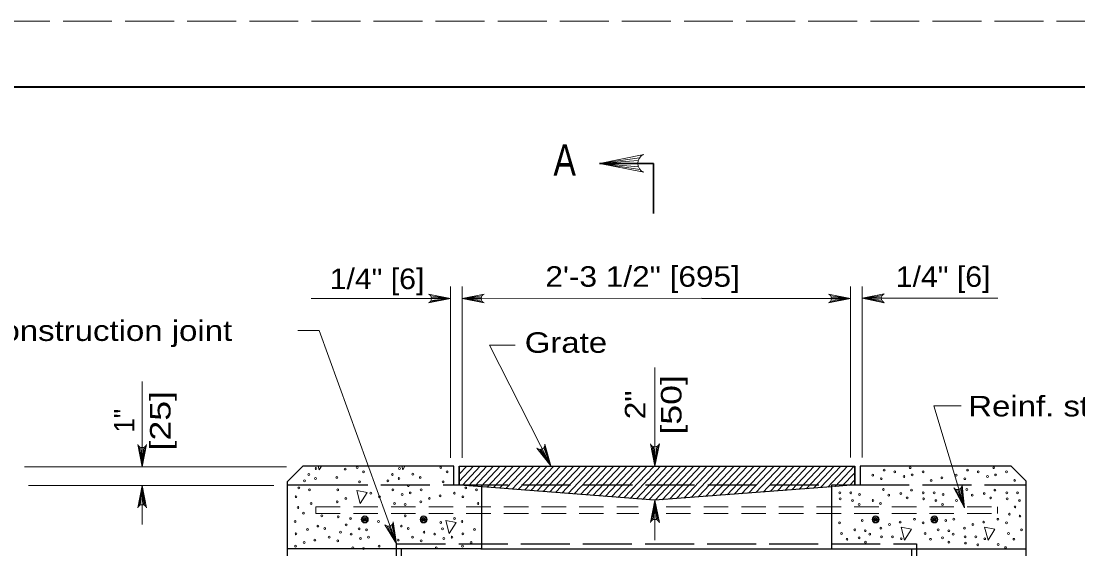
# Model space of a CAD drawing. Extents: x 1083.1 to 1117.1, y 697.4 to 719.4.
# Drawn here: x 1091.89 to 1099.92, y 715.34 to 719.35 of the extents above; entities that cross this region are included whole.
import ezdxf
from ezdxf.enums import TextEntityAlignment as Align

# ---------------------------------------------------------------- set-up
doc = ezdxf.new("R2010")
doc.units = 0
doc.header["$LTSCALE"] = 0.062
doc.linetypes.add('LONG_DASHED', pattern=[7.5, 6, -1.5])
doc.linetypes.add('MEDIUM_DASHED', pattern=[4.5, 3, -1.5])
doc.layers.add('1', color=7, linetype='Continuous', lineweight=13)

msp = doc.modelspace()

# ---------------------------------------------------------------- linework, layer by layer
at = {"layer": '1', "lineweight": 25}
for p, q in [((1085.12642, 718.85408), (1116.62642, 718.85408)), ((1095.18008, 715.82492), (1095.18008, 715.96742)), ((1095.18008, 715.82492), (1095.18008, 715.96742)), ((1095.22233, 715.82492), (1095.22233, 715.96742)), ((1095.22233, 715.96742), (1095.22233, 715.82492)), ((1096.8025, 715.96742), (1098.22792, 715.96742)), ((1098.22792, 715.96742), (1098.22792, 715.82492)), ((1098.22792, 715.82492), (1098.22792, 715.96742)), ((1098.22792, 715.82492), (1098.22792, 715.96742)), ((1098.27017, 715.96742), (1098.27017, 715.82492)), ((1095.18008, 715.82492), (1095.22233, 715.82492)), ((1095.39367, 715.33867), (1095.39367, 715.82492)), ((1098.05058, 715.82492), (1098.05058, 715.33867)), ((1098.22792, 715.82492), (1098.27017, 715.82492)), ((1095.38683, 715.33867), (1093.91333, 715.33867)), ((1094.78358, 711.34008), (1094.78358, 715.33867)), ((1095.38683, 715.33867), (1098.05058, 715.33867)), ((1098.05058, 715.33867), (1098.64775, 715.33867)), ((1098.64775, 715.33867), (1099.53092, 715.33867)), ((1098.65942, 715.33867), (1098.65942, 711.32025))]:
    msp.add_line(p, q, dxfattribs=at)
at = {"layer": '1'}
for p, q in [((1096.59217, 718.31417), (1096.28758, 718.2715)), ((1096.58192, 718.29308), (1096.28758, 718.2715)), ((1096.57875, 718.2715), (1096.28758, 718.2715)), ((1096.58417, 718.24417), (1096.28758, 718.2715)), ((1096.59575, 718.22442), (1096.28758, 718.2715)), ((1095.1565, 716.03125), (1095.1565, 717.33425)), ((1095.243, 716.03142), (1095.243, 717.33425)), ((1098.19683, 716.03333), (1098.19683, 717.33425)), ((1098.28442, 716.0335), (1098.28442, 717.33425)), ((1095.00425, 717.26458), (1095.1565, 717.24325)), ((1095.00942, 717.25408), (1095.1565, 717.24325)), ((1095.39533, 717.26475), (1095.243, 717.24342)), ((1095.39017, 717.25417), (1095.243, 717.24342)), ((1098.0445, 717.26517), (1098.19683, 717.24383)), ((1098.04967, 717.25458), (1098.19683, 717.24383)), ((1098.43675, 717.26683), (1098.28442, 717.2455)), ((1098.43158, 717.25625), (1098.28442, 717.2455)), ((1094.09683, 717.24325), (1095.1565, 717.24325)), ((1095.00242, 717.21975), (1095.1565, 717.24325)), ((1095.00825, 717.22958), (1095.1565, 717.24325)), ((1095.011, 717.24325), (1095.1565, 717.24325)), ((1095.243, 717.24342), (1097.06667, 717.24508)), ((1095.38858, 717.24342), (1095.243, 717.24342)), ((1095.39125, 717.22975), (1095.243, 717.24342)), ((1095.39708, 717.21983), (1095.243, 717.24342)), ((1097.06667, 717.24442), (1098.19683, 717.24383)), ((1098.04275, 717.22033), (1098.19683, 717.24383)), ((1098.04858, 717.23017), (1098.19683, 717.24383)), ((1098.05125, 717.24383), (1098.19683, 717.24383)), ((1098.43, 717.2455), (1098.28442, 717.2455)), ((1098.43267, 717.23183), (1098.28442, 717.2455)), ((1098.4385, 717.222), (1098.28442, 717.2455)), ((1099.31633, 717.2455), (1098.28442, 717.2455)), ((1093.99583, 716.999), (1094.15825, 716.999)), ((1094.15825, 716.999), (1094.74617, 715.37608)), ((1095.45125, 716.8885), (1095.64567, 716.8885)), ((1095.45125, 716.8885), (1095.91917, 715.97025)), ((1096.70908, 715.96925), (1096.70908, 716.71992)), ((1092.8115, 715.96408), (1092.8115, 716.613)), ((1099.06167, 715.65175), (1098.82808, 716.42783)), ((1099.03633, 716.42783), (1098.82808, 716.42783)), ((1096.73258, 716.12333), (1096.70908, 715.96925)), ((1092.79017, 716.11642), (1092.8115, 715.96408)), ((1092.80075, 716.11125), (1092.8115, 715.96408)), ((1092.835, 716.11817), (1092.8115, 715.96408)), ((1092.82517, 716.11242), (1092.8115, 715.96408)), ((1092.8115, 716.10967), (1092.8115, 715.96408)), ((1095.83075, 716.09608), (1095.91917, 715.97025)), ((1095.8425, 716.09633), (1095.91917, 715.97025)), ((1095.85283, 716.09983), (1095.91917, 715.97025)), ((1095.86375, 716.1085), (1095.91917, 715.97025)), ((1095.86983, 716.11817), (1095.91917, 715.97025)), ((1096.68775, 716.1215), (1096.70908, 715.96925)), ((1096.69833, 716.11642), (1096.70908, 715.96925)), ((1096.72275, 716.1175), (1096.70908, 715.96925)), ((1096.70908, 716.11483), (1096.70908, 715.96925)), ((1091.9165, 715.96408), (1093.91008, 715.96408)), ((1095.22233, 715.85258), (1095.33083, 715.96742)), ((1095.22233, 715.90633), (1095.28008, 715.96742)), ((1095.22233, 715.96008), (1095.22933, 715.96742)), ((1095.24533, 715.82308), (1095.38158, 715.96742)), ((1095.29258, 715.81942), (1095.43233, 715.96742)), ((1095.33983, 715.81567), (1095.48308, 715.96742)), ((1095.38708, 715.812), (1095.53383, 715.96742)), ((1095.43433, 715.80833), (1095.58458, 715.96742)), ((1095.48158, 715.80458), (1095.63533, 715.96742)), ((1095.52883, 715.80092), (1095.68617, 715.96742)), ((1095.57608, 715.79717), (1095.73683, 715.96742)), ((1095.62333, 715.7935), (1095.78758, 715.96742)), ((1095.67058, 715.78975), (1095.83833, 715.96742)), ((1095.71783, 715.78608), (1095.88908, 715.96742)), ((1095.76508, 715.78233), (1095.93992, 715.96742)), ((1095.81225, 715.77867), (1095.99058, 715.96742)), ((1095.85958, 715.77492), (1096.04133, 715.96742)), ((1095.90683, 715.77117), (1096.09208, 715.96742)), ((1095.954, 715.7675), (1096.14283, 715.96742)), ((1096.00125, 715.76375), (1096.19367, 715.96742)), ((1096.0485, 715.76008), (1096.24442, 715.96742)), ((1096.09575, 715.75633), (1096.29508, 715.96742)), ((1096.143, 715.75258), (1096.34583, 715.96742)), ((1096.19025, 715.74892), (1096.39658, 715.96742)), ((1096.2375, 715.74517), (1096.44742, 715.96742)), ((1096.28475, 715.7415), (1096.49817, 715.96742)), ((1096.332, 715.73775), (1096.54892, 715.96742)), ((1096.37925, 715.73408), (1096.59958, 715.96742)), ((1096.4265, 715.73033), (1096.65033, 715.96742)), ((1096.47375, 715.72658), (1096.7, 715.96617)), ((1096.61542, 715.71558), (1096.85275, 715.96675)), ((1096.65708, 715.867), (1096.75192, 715.96742)), ((1096.66275, 715.71183), (1096.90275, 715.966)), ((1096.71008, 715.70825), (1096.95492, 715.96742)), ((1096.73483, 715.89558), (1096.80267, 715.96742)), ((1096.76483, 715.71242), (1097.00567, 715.96742)), ((1096.81958, 715.71667), (1097.05642, 715.96742)), ((1096.87433, 715.72083), (1097.10717, 715.96742)), ((1096.929, 715.72508), (1097.15783, 715.96742)), ((1096.98367, 715.72925), (1097.20867, 715.96742)), ((1097.03842, 715.73342), (1097.25942, 715.96742)), ((1097.09317, 715.73767), (1097.31017, 715.96742)), ((1097.14792, 715.74192), (1097.36092, 715.96742)), ((1097.20267, 715.74608), (1097.41167, 715.96742)), ((1097.25742, 715.75033), (1097.46242, 715.96742)), ((1097.31208, 715.75458), (1097.51317, 715.96742)), ((1097.36683, 715.75875), (1097.56392, 715.96742)), ((1097.42158, 715.763), (1097.61467, 715.96742)), ((1097.47633, 715.76717), (1097.66542, 715.96742)), ((1097.531, 715.77133), (1097.71617, 715.96742)), ((1097.58575, 715.77558), (1097.76692, 715.96742)), ((1097.6405, 715.77975), (1097.81767, 715.96742)), ((1097.69525, 715.784), (1097.86842, 715.96742)), ((1097.74992, 715.78825), (1097.91925, 715.96742)), ((1097.80467, 715.79242), (1097.97, 715.96742)), ((1097.85942, 715.79658), (1098.02067, 715.96742)), ((1097.91417, 715.80092), (1098.07142, 715.96742)), ((1097.96883, 715.80508), (1098.12217, 715.96742)), ((1098.02358, 715.80925), (1098.173, 715.96742)), ((1098.07833, 715.8135), (1098.22375, 715.96742)), ((1096.56817, 715.71917), (1096.73342, 715.89417)), ((1098.133, 715.81767), (1098.22792, 715.91808)), ((1091.949, 715.81983), (1093.81267, 715.81983)), ((1092.78792, 715.66575), (1092.8115, 715.81983)), ((1092.79783, 715.67158), (1092.8115, 715.81983)), ((1092.8115, 715.52458), (1092.8115, 715.81983)), ((1092.8115, 715.67433), (1092.8115, 715.81983)), ((1092.82225, 715.67275), (1092.8115, 715.81983)), ((1092.83283, 715.66758), (1092.8115, 715.81983)), ((1095.225, 715.82467), (1095.22233, 715.82492)), ((1096.521, 715.723), (1096.6585, 715.8685)), ((1098.22792, 715.82492), (1098.04933, 715.81125)), ((1098.18775, 715.82183), (1098.22792, 715.86433)), ((1099.03975, 715.806), (1099.06167, 715.65175)), ((1098.99725, 715.79142), (1099.06167, 715.65175)), ((1099.00883, 715.78958), (1099.06167, 715.65175)), ((1099.01958, 715.79108), (1099.06167, 715.65175)), ((1099.03192, 715.79758), (1099.06167, 715.65175)), ((1096.6855, 715.55408), (1096.70908, 715.70817)), ((1096.69542, 715.55992), (1096.70908, 715.70817)), ((1096.70908, 715.56258), (1096.70908, 715.70817)), ((1096.71983, 715.56108), (1096.70908, 715.70817)), ((1096.73033, 715.55592), (1096.70908, 715.70817)), ((1096.70908, 715.70817), (1096.70908, 715.40383)), ((1094.67408, 715.512), (1094.74617, 715.37608)), ((1094.68575, 715.51083), (1094.74617, 715.37608)), ((1094.69642, 715.513), (1094.74617, 715.37608)), ((1094.70842, 715.52008), (1094.74617, 715.37608)), ((1094.71567, 715.529), (1094.74617, 715.37608))]:
    msp.add_line(p, q, dxfattribs=at)
at = {"layer": '1', "lineweight": 35}
for p, q in [((1096.28758, 718.2715), (1096.69883, 718.2715)), ((1096.69883, 718.2715), (1096.69883, 717.89125))]:
    msp.add_line(p, q, dxfattribs=at)
at = {"layer": '1', "linetype": 'LONG_DASHED', "lineweight": 25}
for p, q in [((1093.91333, 715.82492), (1094.15475, 715.82492)), ((1094.15475, 715.82492), (1095.18008, 715.82492)), ((1095.22233, 715.82492), (1098.22792, 715.82492)), ((1098.27017, 715.82492), (1099.53092, 715.82492)), ((1094.74617, 714.6735), (1094.74617, 715.37608))]:
    msp.add_line(p, q, dxfattribs=at)
at = {"layer": '1', "linetype": 'LONG_DASHED'}
for p, q in [((1094.13142, 715.609), (1094.13142, 715.65775)), ((1099.31175, 715.65775), (1099.31175, 715.609))]:
    msp.add_line(p, q, dxfattribs=at)
at = {"layer": '1', "linetype": 'MEDIUM_DASHED'}
for p, q in [((1094.13142, 715.65775), (1096.58208, 715.65775)), ((1096.79408, 715.65775), (1099.31175, 715.65775)), ((1094.13142, 715.609), (1096.58558, 715.609)), ((1096.79408, 715.609), (1099.31175, 715.609))]:
    msp.add_line(p, q, dxfattribs=at)
at = {"layer": '1', "linetype": 'LONG_DASHED'}
msp.add_lwpolyline([(1083.12642, 697.35408), (1117.12642, 697.35408), (1117.12642, 719.35408), (1083.12642, 719.35408)], close=True, dxfattribs=at)
at = {"layer": '1', "lineweight": 40}
msp.add_lwpolyline([(1085.12642, 718.85408), (1116.62642, 718.85408), (1116.62642, 697.85408), (1085.12642, 697.85408)], close=True, dxfattribs=at)
msp.add_lwpolyline([(1085.12642, 718.85408), (1116.62642, 718.85408), (1116.62642, 697.85408), (1085.12642, 697.85408)], close=True, dxfattribs=at)
at = {"layer": '1'}
for points in [[(1096.62408, 718.20425), (1096.28758, 718.2715), (1096.62408, 718.33883)], [(1094.98833, 717.20967), (1095.1565, 717.24325), (1094.98833, 717.27692)], [(1095.41125, 717.20975), (1095.243, 717.24342), (1095.41125, 717.27708)], [(1098.02858, 717.21017), (1098.19683, 717.24383), (1098.02858, 717.2775)], [(1098.45267, 717.21183), (1098.28442, 717.2455), (1098.45267, 717.27917)], [(1092.84517, 716.13233), (1092.8115, 715.96408), (1092.77783, 716.13233)], [(1095.8725, 716.13533), (1095.91917, 715.97025), (1095.8125, 716.10467)], [(1096.74267, 716.1375), (1096.70908, 715.96925), (1096.67542, 716.1375)], [(1094.15067, 715.96733), (1094.15767, 715.941), (1094.17442, 715.96733)], [(1094.78517, 715.96733), (1094.792, 715.941), (1094.80875, 715.96733)], [(1092.77783, 715.65167), (1092.8115, 715.81983), (1092.84517, 715.65167)], [(1099.04533, 715.82258), (1099.06167, 715.65175), (1098.98092, 715.80308)], [(1096.67542, 715.54), (1096.70908, 715.70817), (1096.74267, 715.54)], [(1094.72033, 715.54567), (1094.74617, 715.37608), (1094.65708, 715.52275)]]:
    msp.add_lwpolyline(points, dxfattribs=at)
at = {"layer": '1', "lineweight": 25}
for points in [[(1095.18008, 715.96742), (1094.03358, 715.96742), (1093.91333, 715.848)], [(1095.22233, 715.96742), (1096.74292, 715.96742), (1096.8025, 715.96742)], [(1099.53092, 715.85275), (1099.41633, 715.96917), (1098.27017, 715.96742)], [(1093.91333, 715.848), (1093.91333, 711.52217), (1093.91333, 711.41925)], [(1098.04933, 715.81125), (1096.70908, 715.70817), (1095.39975, 715.811), (1095.225, 715.82467)], [(1099.53092, 711.424), (1099.53092, 711.52217), (1099.53092, 715.85275)]]:
    msp.add_lwpolyline(points, dxfattribs=at)
at = {"layer": '1'}
for points in [[(1094.44342, 715.78183), (1094.46908, 715.6845), (1094.52125, 715.76667)], [(1095.12025, 715.5535), (1095.14592, 715.45625), (1095.19817, 715.53842)], [(1098.58092, 715.5035), (1098.6065, 715.40617), (1098.65875, 715.48825)], [(1099.21525, 715.5035), (1099.24092, 715.40617), (1099.29317, 715.48825)]]:
    msp.add_lwpolyline(points, close=True, dxfattribs=at)
at = {"layer": '1', "linetype": 'LONG_DASHED', "lineweight": 25}
msp.add_lwpolyline([(1094.74617, 715.37608), (1098.69675, 715.37608), (1098.69675, 714.6735)], dxfattribs=at)
at = {"layer": '1'}
for centre, radius in [((1094.50414, 715.56232), 0.02655), ((1094.50414, 715.56232), 0.01987), ((1094.50414, 715.56232), 0.01149), ((1094.50414, 715.56232), 0.00431), ((1094.95114, 715.56232), 0.02655), ((1094.95114, 715.56232), 0.02655), ((1094.95114, 715.56232), 0.01987), ((1094.95114, 715.56232), 0.01149), ((1094.95114, 715.56232), 0.00431), ((1098.38657, 715.56232), 0.02655), ((1098.38657, 715.56232), 0.01987), ((1098.38657, 715.56232), 0.01149), ((1098.38657, 715.56232), 0.00431), ((1098.83357, 715.56232), 0.02655), ((1098.83357, 715.56232), 0.02655), ((1098.83357, 715.56232), 0.01987), ((1098.83357, 715.56232), 0.01149), ((1098.83357, 715.56232), 0.00431)]:
    msp.add_circle(centre, radius, dxfattribs=at)
for centre, radius, start, end in [((1096.65122, 718.27159), 0.07261, 112.08782, 247.91395), ((1094.97473, 717.24333), 0.03631, 292.08605, 67.91218), ((1095.42481, 717.24346), 0.03631, 112.08782, 247.91395), ((1098.01503, 717.24389), 0.03631, 292.08605, 67.91218), ((1098.46625, 717.24556), 0.03631, 112.08782, 247.91395), ((1092.81145, 716.14592), 0.03631, 202.08782, 337.91395), ((1095.83625, 716.13207), 0.03631, 229.21576, 5.04189), ((1096.70902, 716.15105), 0.03631, 202.08782, 337.91395), ((1099.00913, 715.8258), 0.03631, 218.87464, 354.70076), ((1092.81152, 715.63806), 0.03631, 22.08782, 157.91395), ((1096.7091, 715.52638), 0.03631, 22.08782, 157.91395), ((1094.68404, 715.54698), 0.03631, 222.05181, 357.87794)]:
    msp.add_arc(centre, radius, start, end, dxfattribs=at)
for centre in [(1094.44639, 715.95819), (1095.08079, 715.95819), (1098.64944, 715.95615), (1099.28385, 715.95615), (1094.07897, 715.90468), (1094.12945, 715.87474), (1094.13289, 715.95091), (1094.29133, 715.88291), (1094.35477, 715.94638), (1094.49466, 715.92522), (1094.71337, 715.90468), (1094.76386, 715.87474), (1094.76729, 715.95091), (1094.86922, 715.90647), (1094.92573, 715.88291), (1095.12906, 715.92522), (1098.36476, 715.89968), (1098.4513, 715.93869), (1098.53208, 715.92447), (1098.60229, 715.89), (1098.66398, 715.90091), (1098.74709, 715.92531), (1098.89041, 715.8788), (1098.99916, 715.89968), (1099.0857, 715.93869), (1099.16648, 715.92447), (1099.23669, 715.89), (1099.29838, 715.90091), (1099.38149, 715.92531), (1094.00241, 715.80192), (1094.0455, 715.8566), (1094.46468, 715.84815), (1094.6799, 715.8566), (1094.83496, 715.81938), (1095.09908, 715.84815), (1095.27122, 715.80192), (1098.42989, 715.87248), (1098.809, 715.85977), (1099.06429, 715.87248), (1099.4434, 715.85977), (1093.981, 715.7357), (1094.0832, 715.7877), (1094.2982, 715.78854), (1094.36011, 715.723), (1094.55027, 715.76291), (1094.61541, 715.7357), (1094.7176, 715.7877), (1094.7878, 715.75322), (1094.8495, 715.76414), (1094.93261, 715.78854), (1094.99451, 715.723), (1095.07593, 715.74203), (1095.18468, 715.76291), (1095.24981, 715.7357), (1095.352, 715.7877), (1098.1147, 715.76546), (1098.11723, 715.71923), (1098.19696, 715.76546), (1098.26457, 715.75186), (1098.44532, 715.79087), (1098.48645, 715.74733), (1098.57807, 715.75914), (1098.62634, 715.72617), (1098.65917, 715.78634), (1098.7491, 715.76546), (1098.75163, 715.71923), (1098.83136, 715.76546), (1098.89897, 715.75186), (1099.07973, 715.79087), (1099.12086, 715.74733), (1099.21247, 715.75914), (1099.26074, 715.72617), (1099.29357, 715.78634), (1099.3835, 715.76546), (1099.38604, 715.71923), (1099.46576, 715.76546), (1093.99644, 715.6541), (1094.09578, 715.68315), (1094.29509, 715.6958), (1094.73018, 715.68315), (1094.81101, 715.67615), (1094.92949, 715.6958), (1095.36458, 715.68315), (1098.21065, 715.70563), (1098.26114, 715.67568), (1098.3665, 715.70742), (1098.42301, 715.68386), (1098.84505, 715.70563), (1098.89554, 715.67568), (1099.0009, 715.70742), (1099.44599, 715.65755), (1099.47945, 715.70563), (1094.03757, 715.61055), (1094.17746, 715.5894), (1094.30275, 715.58246), (1094.39617, 715.56886), (1094.81186, 715.5894), (1095.18642, 715.57065), (1098.28508, 715.55417), (1098.68196, 715.56385), (1098.91949, 715.55417), (1098.98118, 715.56509), (1099.31636, 715.56385), (1099.4029, 715.60287), (1099.48368, 715.58865), (1093.97413, 715.54708), (1094.06866, 715.48697), (1094.14748, 715.51233), (1094.19971, 715.49329), (1094.3627, 715.52078), (1094.4604, 715.49178), (1094.51776, 715.48356), (1094.60853, 715.54708), (1094.78188, 715.51233), (1094.83412, 715.49329), (1095.08106, 715.53891), (1095.0948, 715.49178), (1095.24294, 715.54708), (1095.33746, 715.48697), (1098.11269, 715.53665), (1098.22746, 715.4841), (1098.30829, 715.4771), (1098.42677, 715.49675), (1098.49179, 715.52395), (1098.57321, 715.54298), (1098.74709, 715.53665), (1098.86186, 715.4841), (1098.9427, 715.4771), (1099.06117, 715.49675), (1099.1262, 715.52395), (1099.20761, 715.54298), (1099.38149, 715.53665), (1099.49626, 715.4841), (1093.981, 715.45272), (1094.12433, 715.4062), (1094.23307, 715.42708), (1094.2982, 715.39988), (1094.31962, 715.46609), (1094.4004, 715.45188), (1094.4706, 715.4174), (1094.5323, 715.42831), (1094.75873, 715.4062), (1094.86748, 715.42708), (1094.93261, 715.39988), (1094.95402, 715.46609), (1095.0348, 715.45188), (1095.10501, 715.4174), (1095.1667, 715.42831), (1095.24981, 715.45272), (1098.12812, 715.45505), (1098.16925, 715.4115), (1098.26087, 715.42331), (1098.34197, 715.45051), (1098.4319, 715.42964), (1098.51416, 715.42964), (1098.58177, 715.41604), (1098.76253, 715.45505), (1098.80366, 715.4115), (1098.89527, 715.42331), (1098.97637, 715.45051), (1099.0663, 715.42964), (1099.14856, 715.42964), (1099.21618, 715.41604), (1099.39693, 715.45505), (1099.43806, 715.4115), (1093.97788, 715.35997), (1094.04291, 715.38717), (1094.41298, 715.34732), (1094.49381, 715.34033), (1094.61229, 715.35997), (1095.04738, 715.34732), (1095.24669, 715.35997), (1095.31172, 715.38717), (1098.30914, 715.39035), (1098.94354, 715.39035), (1099.06884, 715.3834), (1099.16225, 715.3698), (1099.3181, 715.3716), (1099.37462, 715.34803)]:
    msp.add_ellipse(centre, major_axis=(0, 0.00718), ratio=0.944544, dxfattribs=at)

# ---------------------------------------------------------------- texts
for s, height, width, p in [('A', 0.24, 0.8, (1095.93758, 718.17775)), ('2\'-3 1/2" [695]', 0.156, 1.15, (1095.8765, 717.33308)), ('Construction joint', 0.156, 1.2, (1091.56175, 716.92083)), ('Reinf. steel', 0.156, 1.2, (1099.09075, 716.34642))]:
    msp.add_text(s, height=height, dxfattribs=dict(at, width=width)).set_placement(p)
for s, width, p in [('1/4" [6]', 1.1, (1098.89963, 717.33233)), ('1/4" [6]', 1.1, (1094.59671, 717.31533)), ('Grate', 1.2, (1096.03279, 716.83042))]:
    msp.add_text(s, height=0.156, dxfattribs=dict(at, width=width)).set_placement(p, align=Align.CENTER)
for s, width, p in [('[50]', 1.3, (1096.91092, 716.43429)), ('2"', 1.15, (1096.63683, 716.43429)), ('[25]', 1.3, (1093.02742, 716.31354)), ('1"', 0.95, (1092.75333, 716.31354))]:
    msp.add_text(s, height=0.156, rotation=90, dxfattribs=dict(at, width=width)).set_placement(p, align=Align.CENTER)

doc.saveas('drawing.dxf')
